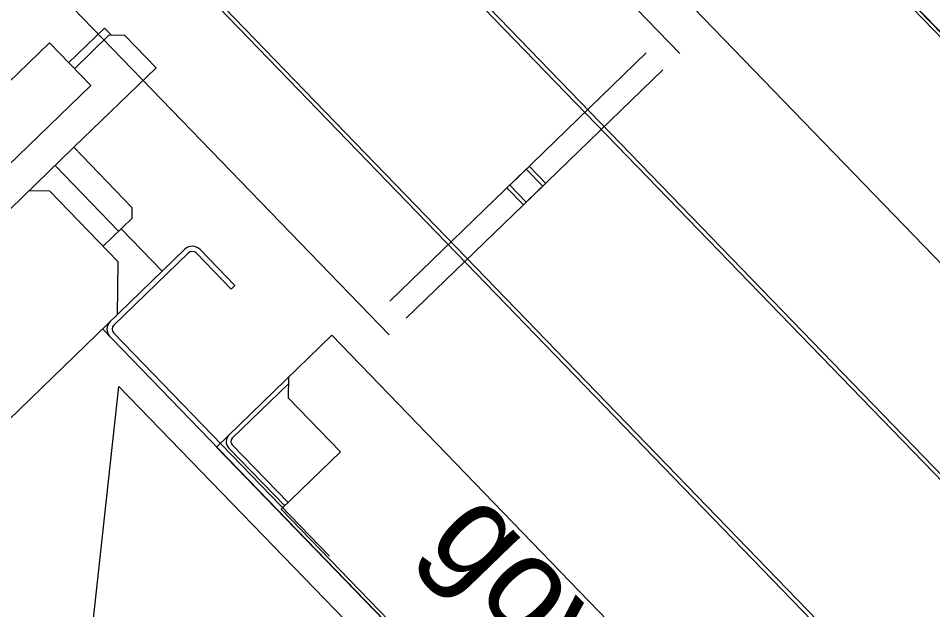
# Model space of a CAD drawing. Extents: x 468143 to 491361, y 1438528 to 1468730.
# Drawn here: x 490340.828 to 490342.432, y 1467631.034 to 1467632.071 of the extents above; entities that cross this region are included whole.
import ezdxf

# ---------------------------------------------------------------- set-up
doc = ezdxf.new("R2010")
doc.units = 0
doc.layers.add('Xreference_dp', color=7, linetype='Continuous')

msp = doc.modelspace()

# ---------------------------------------------------------------- linework, layer by layer
at = {"layer": 'Xreference_dp'}
for p, q in [((490342.655, 1467631.0551), (490340.9382, 1467632.829)), ((490340.9382, 1467632.829), (490345.7482, 1467627.859)), ((490342.655, 1467631.0551), (490340.9382, 1467632.829)), ((490340.9382, 1467632.829), (490345.7482, 1467627.859)), ((490342.65, 1467631.0502), (490340.9332, 1467632.8242)), ((490340.9332, 1467632.8242), (490345.7432, 1467627.8542)), ((490342.65, 1467631.0502), (490340.9332, 1467632.8242)), ((490340.9332, 1467632.8242), (490345.7432, 1467627.8542)), ((490341.3513, 1467632.6675), (490341.9888, 1467632.0088)), ((490341.3513, 1467632.6675), (490341.9888, 1467632.0088)), ((490342.4105, 1467630.8184), (490340.6937, 1467632.5924)), ((490340.6937, 1467632.5924), (490345.5037, 1467627.6224)), ((490342.4105, 1467630.8184), (490340.6937, 1467632.5924)), ((490340.6937, 1467632.5924), (490345.5037, 1467627.6224)), ((490342.4155, 1467630.8233), (490340.6987, 1467632.5972)), ((490340.6987, 1467632.5972), (490345.5087, 1467627.6272)), ((490342.4155, 1467630.8233), (490340.6987, 1467632.5972)), ((490340.6987, 1467632.5972), (490345.5087, 1467627.6272)), ((490341.9949, 1467632.5118), (490343.0421, 1467631.4297)), ((490341.9949, 1467632.5118), (490345.8182, 1467628.5613)), ((490341.9949, 1467632.5118), (490343.0421, 1467631.4297)), ((490341.9949, 1467632.5118), (490345.8182, 1467628.5613)), ((490343.9356, 1467630.5072), (490342.1953, 1467632.3054)), ((490343.9356, 1467630.5072), (490342.1953, 1467632.3054)), ((490342.3004, 1467632.188), (490342.7795, 1467631.6929)), ((490342.3004, 1467632.188), (490342.7795, 1467631.6929)), ((490340.8416, 1467632.1742), (490341.479, 1467631.5155)), ((490340.8416, 1467632.1742), (490341.479, 1467631.5155)), ((490341.9929, 1467632.1095), (490342.5815, 1467631.5012)), ((490341.9929, 1467632.1095), (490342.5815, 1467631.5012)), ((490340.9167, 1467631.9927), (490340.9796, 1467632.0535)), ((490340.9167, 1467631.9927), (490340.9796, 1467632.0535)), ((490340.9269, 1467631.9822), (490340.9874, 1467632.0407)), ((490340.9269, 1467631.9822), (490340.9874, 1467632.0407)), ((490340.9796, 1467632.0535), (490340.992, 1467632.0407)), ((490340.9796, 1467632.0535), (490340.992, 1467632.0407)), ((490341.0152, 1467632.0403), (490340.9874, 1467632.0407)), ((490341.0152, 1467632.0403), (490340.9874, 1467632.0407)), ((490341.07, 1467631.9837), (490341.0152, 1467632.0403)), ((490341.07, 1467631.9837), (490341.0152, 1467632.0403)), ((490339.5807, 1467630.767), (490340.8831, 1467632.0275)), ((490339.5807, 1467630.767), (490340.8831, 1467632.0275)), ((490340.8831, 1467632.0275), (490340.9555, 1467631.9526)), ((490340.8831, 1467632.0275), (490340.9555, 1467631.9526)), ((490341.9299, 1467632.0098), (490341.6904, 1467631.778)), ((490341.9299, 1467632.0098), (490341.6904, 1467631.778)), ((490341.07, 1467631.9837), (490340.9259, 1467631.8443)), ((490341.07, 1467631.9837), (490340.9259, 1467631.8443)), ((490341.9588, 1467631.9799), (490341.7193, 1467631.7481)), ((490341.9588, 1467631.9799), (490341.7193, 1467631.7481)), ((490340.9555, 1467631.9526), (490339.6532, 1467630.6922)), ((490340.9555, 1467631.9526), (490339.6532, 1467630.6922)), ((490339.693, 1467630.651), (490340.9259, 1467631.8443)), ((490339.693, 1467630.651), (490340.9259, 1467631.8443)), ((490341.0284, 1467631.7384), (490340.9259, 1467631.8443)), ((490341.0284, 1467631.7384), (490340.9259, 1467631.8443)), ((490341.0045, 1467631.6971), (490340.8929, 1467631.8123)), ((490341.0045, 1467631.6971), (490340.8929, 1467631.8123)), ((490341.48, 1467631.5744), (490341.7195, 1467631.8062)), ((490341.48, 1467631.5744), (490341.7195, 1467631.8062)), ((490341.7485, 1467631.7763), (490341.7195, 1467631.8062)), ((490341.7485, 1467631.7763), (490341.7195, 1467631.8062)), ((490341.7535, 1467631.7811), (490341.7245, 1467631.8111)), ((490341.7535, 1467631.7811), (490341.7245, 1467631.8111)), ((490340.8479, 1467631.7687), (490340.8832, 1467631.7682)), ((490340.8479, 1467631.7687), (490340.8832, 1467631.7682)), ((490340.8832, 1467631.7682), (490341.0032, 1467631.6442)), ((490340.8832, 1467631.7682), (490341.0032, 1467631.6442)), ((490341.509, 1467631.5445), (490341.7485, 1467631.7763)), ((490341.509, 1467631.5445), (490341.7485, 1467631.7763)), ((490341.7143, 1467631.7432), (490341.6853, 1467631.7731)), ((490341.7143, 1467631.7432), (490341.6853, 1467631.7731)), ((490341.7193, 1467631.7481), (490341.6904, 1467631.778)), ((490341.7193, 1467631.7481), (490341.6904, 1467631.778)), ((490341.0281, 1467631.7199), (490341.0284, 1467631.7384)), ((490341.0281, 1467631.7199), (490341.0284, 1467631.7384)), ((490340.9774, 1467631.6708), (490341.0281, 1467631.7199)), ((490340.9774, 1467631.6708), (490341.0281, 1467631.7199)), ((490341.081, 1467631.6273), (490341.0091, 1467631.7015)), ((490341.081, 1467631.6273), (490341.0091, 1467631.7015)), ((490339.8764, 1467630.4615), (490341.1206, 1467631.6656)), ((490339.8764, 1467630.4615), (490341.1206, 1467631.6656)), ((490340.996, 1467631.5325), (490341.1269, 1467631.6591)), ((490340.996, 1467631.5325), (490341.1269, 1467631.6591)), ((490341.1408, 1467631.6589), (490341.2018, 1467631.5958)), ((490341.1408, 1467631.6589), (490341.2018, 1467631.5958)), ((490341.1473, 1467631.6651), (490341.2083, 1467631.6021)), ((490341.1473, 1467631.6651), (490341.2083, 1467631.6021)), ((490341.0032, 1467631.6442), (490341.0017, 1467631.5505)), ((490341.0032, 1467631.6442), (490341.0017, 1467631.5505)), ((490341.2018, 1467631.5958), (490341.2083, 1467631.6021)), ((490341.2018, 1467631.5958), (490341.2083, 1467631.6021)), ((490340.9762, 1467631.5258), (490342.0234, 1467630.4438)), ((490340.9762, 1467631.5258), (490344.7995, 1467627.5754)), ((490340.9762, 1467631.5258), (490342.0234, 1467630.4438)), ((490340.9762, 1467631.5258), (490344.7995, 1467627.5754)), ((490341.3742, 1467631.1276), (490340.9958, 1467631.5186)), ((490341.3742, 1467631.1276), (490340.9958, 1467631.5186)), ((490341.1759, 1467631.3188), (490341.3783, 1467631.5147)), ((490341.1759, 1467631.3188), (490341.3783, 1467631.5147)), ((490341.3783, 1467631.5147), (490341.967, 1467630.9065)), ((490341.3783, 1467631.5147), (490341.967, 1467630.9065)), ((490341.2037, 1467631.3343), (490341.3027, 1467631.4301)), ((490341.2037, 1467631.3343), (490341.3027, 1467631.4301)), ((490341.3023, 1467631.4046), (490341.3029, 1467631.4417)), ((490341.3023, 1467631.4046), (490341.3029, 1467631.4417)), ((490340.0921, 1467623.0751), (490341.0051, 1467631.4252)), ((490340.0921, 1467623.0751), (490341.0051, 1467631.4252)), ((490341.0051, 1467631.4252), (490344.7364, 1467627.5699)), ((490341.0051, 1467631.4252), (490344.7364, 1467627.5699)), ((490341.3936, 1467631.3103), (490341.3023, 1467631.4046)), ((490341.3936, 1467631.3103), (490341.3023, 1467631.4046)), ((490342.9162, 1467629.5206), (490341.1759, 1467631.3188)), ((490342.9162, 1467629.5206), (490341.1759, 1467631.3188)), ((490341.3016, 1467631.2213), (490341.2035, 1467631.3227)), ((490341.3016, 1467631.2213), (490341.2035, 1467631.3227)), ((490341.2957, 1467631.2156), (490341.1976, 1467631.317)), ((490341.2957, 1467631.2156), (490341.1976, 1467631.317)), ((490341.2898, 1467631.2099), (490341.3936, 1467631.3103)), ((490341.2898, 1467631.2099), (490341.3936, 1467631.3103)), ((490341.2898, 1467631.2099), (490341.769, 1467630.7148)), ((490341.2898, 1467631.2099), (490341.769, 1467630.7148))]:
    msp.add_line(p, q, dxfattribs=at)
for centre, radius, start, end in [((490341.1337, 1467631.652), 0.0189, 44.063, 134.063), ((490341.1337, 1467631.652), 0.0189, 44.063, 134.063), ((490341.1337, 1467631.652), 0.00984, 44.063, 134.063), ((490341.1337, 1467631.652), 0.00984, 44.063, 134.063), ((490341.0029, 1467631.5254), 0.0189, 134.063, 224.063), ((490341.0029, 1467631.5254), 0.0189, 134.063, 224.063), ((490341.0029, 1467631.5254), 0.00984, 134.063, 224.063), ((490341.0029, 1467631.5254), 0.00984, 134.063, 224.063), ((490341.2094, 1467631.3284), 0.0164, 134.063, 224.063), ((490341.2094, 1467631.3284), 0.0164, 134.063, 224.063), ((490341.2094, 1467631.3284), 0.0082, 134.063, 224.063), ((490341.2094, 1467631.3284), 0.0082, 134.063, 224.063)]:
    msp.add_arc(centre, radius, start, end, dxfattribs=at)

# ---------------------------------------------------------------- texts
msp.add_text('gov', height=0.16666, rotation=314.063, dxfattribs=at).set_placement((490341.5412, 1467631.15))
msp.add_text('gov', height=0.16666, rotation=314.063, dxfattribs=at).set_placement((490341.5412, 1467631.15))

doc.saveas('drawing.dxf')
